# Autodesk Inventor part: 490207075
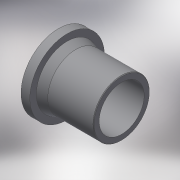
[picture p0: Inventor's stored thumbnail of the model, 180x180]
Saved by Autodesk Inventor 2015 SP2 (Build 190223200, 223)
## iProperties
Created: 2017-07
Part Number: 490207075
Material: Generic
Description: Stub Flange 75
Document SubType Name: Modeling
Designer: Кирилл
Mass: 341.535 g
Surface Area: 751.176 cm^2
Volume: 341.535 cm^3
Density: 1 g/cm^3
Appearance: Default
Author: Кирилл
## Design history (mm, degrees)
derived "490207.ipt"
feature "Solid1::490207.ipt"
tag "TaggingFeature1"
body "Solid1"
other parameters: "d1" = 89, "d2" = 75, "d4" = 122, "d5" = 16, "d6" = 92, "d16" = 75, "d17" = 1.5, "d18" = 1.5, "d19" = 1.5, "d21" = 1.5, "d24" = 1.5, "d25" = 1.5, "d26" = 0.75, "d27" = 0, "d32" = 0.75, "d_" = 75, "L_1" = 92, "D_" = 122, "D_1" = 89, "a_" = 16
